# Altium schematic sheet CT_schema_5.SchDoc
size 430 x 414 mm
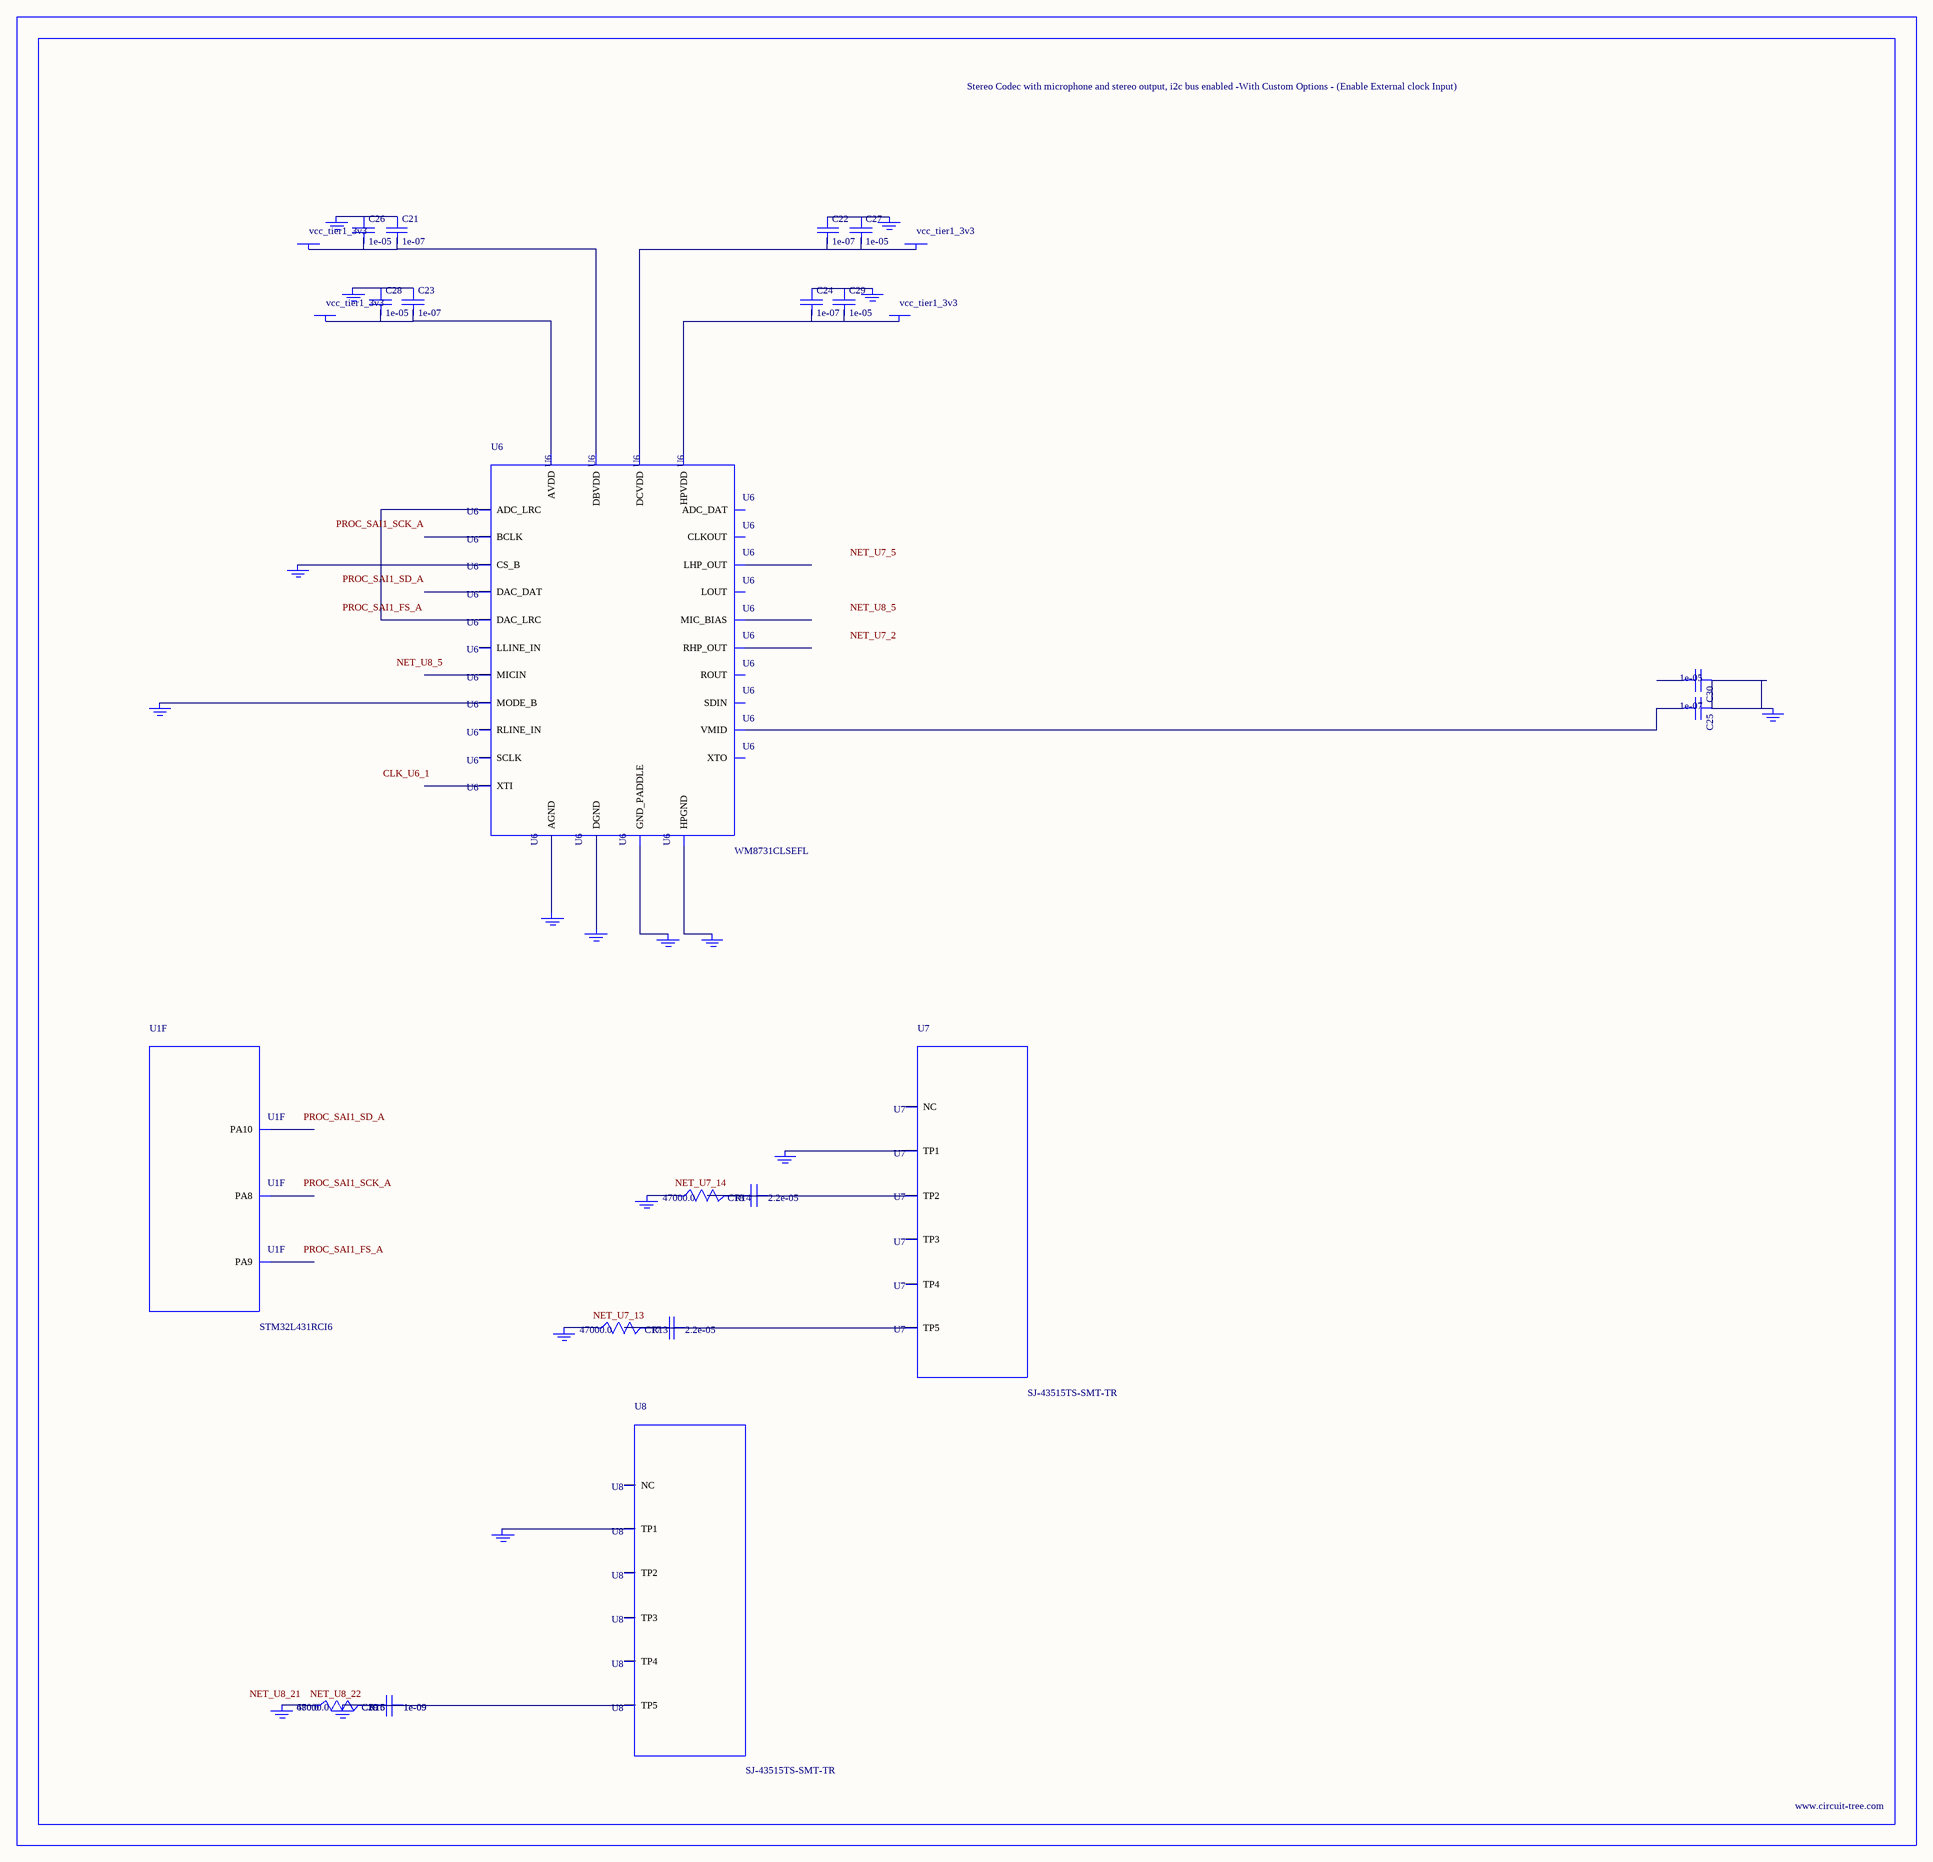
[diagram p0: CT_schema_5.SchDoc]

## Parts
BORDER4  (no value)
C17  2.2e-05  [C1210]
C18  2.2e-05  [C1210]
C19  1e-09  [C0402]
C20  1e-09  [C0402]
C21  1e-07  [C0402]
C22  1e-07  [C0402]
C23  1e-07  [C0402]
C24  1e-07  [C0402]
C25  1e-07  [C0402]
C26  1e-05  [C0805]
C27  1e-05  [C0805]
C28  1e-05  [C0805]
C29  1e-05  [C0805]
C30  1e-05  [C0805]
GND_INSTANCE_4_0  (no value)
GND_INSTANCE_4_1  (no value)
GND_INSTANCE_4_2  (no value)
GND_INSTANCE_4_3  (no value)
GND_INSTANCE_4_4  (no value)
GND_INSTANCE_4_5  (no value)
GND_INSTANCE_4_6  (no value)
GND_INSTANCE_4_7  (no value)
GND_INSTANCE_4_8  (no value)
GND_INSTANCE_4_9  (no value)
GND_INSTANCE_4_10  (no value)
GND_INSTANCE_4_11  (no value)
GND_INSTANCE_4_12  (no value)
GND_INSTANCE_4_13  (no value)
GND_INSTANCE_4_14  (no value)
GND_INSTANCE_4_15  (no value)
GND_INSTANCE_4_16  (no value)
POWER_INSTANCE_4_0  vcc_tier1_3v3
POWER_INSTANCE_4_1  vcc_tier1_3v3
POWER_INSTANCE_4_2  vcc_tier1_3v3
POWER_INSTANCE_4_3  vcc_tier1_3v3
R13  47000.0  [R0603]
R14  47000.0  [R0603]
R15  47000.0  [R0603]
R16  680.0  [R0603]
U1  STM32L431RCI6  [UFBGA64]  (part F of 6)
U6  WM8731CLSEFL  [QFN-28]
U7  SJ-43515TS-SMT-TR  [SJ-43515TS-SMT-TR]
U8  SJ-43515TS-SMT-TR  [SJ-43515TS-SMT-TR]

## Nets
NetC17_1: C17.1 C17.2 R13.2 U7.5(TP5)
NetC18_1: C18.1 C18.2 R14.2 U7.2(TP2)
NetC19_1: C19.1 C19.2 C20.1 C20.2 GND_INSTANCE_4_16.0(GND) R15.2 R16.2 U8.5(TP5)
NetC21_1: C21.1 C26.1 GND_INSTANCE_4_1.0(GND)
NetC21_2: C21.2 C26.2 POWER_INSTANCE_4_1.0(PWR) U6.5(DBVDD)
NetC22_1: C22.1 C27.1 GND_INSTANCE_4_0.0(GND)
NetC22_2: C22.2 C27.2 POWER_INSTANCE_4_0.0(PWR) U6.3(DCVDD)
NetC23_1: C23.1 C28.1 GND_INSTANCE_4_4.0(GND)
NetC23_2: C23.2 C28.2 POWER_INSTANCE_4_3.0(PWR) U6.18(AVDD)
NetC24_1: C24.1 C29.1 GND_INSTANCE_4_2.0(GND)
NetC24_2: C24.2 C29.2 POWER_INSTANCE_4_2.0(PWR) U6.12(HPVDD)
NetC25_1: C25.1 C30.1 GND_INSTANCE_4_5.0(GND)
NetC25_2: C25.2 U6.20(VMID)
NetGND_INSTANCE_4_3_0: GND_INSTANCE_4_3.0(GND) U6.15(HPGND)
NetGND_INSTANCE_4_6_0: GND_INSTANCE_4_6.0(GND) U6.25(MODE_B)
NetGND_INSTANCE_4_7_0: GND_INSTANCE_4_7.0(GND) U6.26(CS_B)
NetGND_INSTANCE_4_8_0: GND_INSTANCE_4_8.0(GND) U6.29(GND_PADDLE)
NetGND_INSTANCE_4_9_0: GND_INSTANCE_4_9.0(GND) U6.4(DGND)
NetGND_INSTANCE_4_10_0: GND_INSTANCE_4_10.0(GND) U6.19(AGND)
NetGND_INSTANCE_4_11_0: GND_INSTANCE_4_11.0(GND) U7.1(TP1)
NetGND_INSTANCE_4_12_0: GND_INSTANCE_4_12.0(GND) R14.1
NetGND_INSTANCE_4_13_0: GND_INSTANCE_4_13.0(GND) R13.1
NetGND_INSTANCE_4_14_0: GND_INSTANCE_4_14.0(GND) U8.1(TP1)
NetGND_INSTANCE_4_15_0: GND_INSTANCE_4_15.0(GND) R15.1 R16.1
NetU6_9: U6.9(DAC_LRC) U6.11(ADC_LRC)

Not connected (* = marked no-connect by the designer): C30 2; U1 C6(PA10) C7(PA9) D7(PA8); U6 1(XTI) 2(XTO) 6(CLKOUT) 7(BCLK) 8(DAC_DAT) 10(ADC_DAT) 13(LHP_OUT) 14(RHP_OUT) 16(LOUT) 17(ROUT) 21(MIC_BIAS) 22(MICIN) 23(RLINE_IN) 24(LLINE_IN) 27(SDIN) 28(SCLK); U7 3(TP3) 4(TP4) 6(NC); U8 2(TP2) 3(TP3) 4(TP4) 6(NC)

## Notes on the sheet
- Labels drawn without touching a wire or pin: CLK_U6_1, NET_U7_2, NET_U7_5, NET_U7_13, NET_U7_14, NET_U8_5, NET_U8_21, NET_U8_22, PROC_SAI1_FS_A, PROC_SAI1_SCK_A, PROC_SAI1_SD_A

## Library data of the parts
BORDER4 = BORDER_PAGE4
C17 C18 = C1210C224K5RACTU
C19 C20 = C0402C102K3RAC
C21-C25 = C0402C104K3RACTU
C26-C30 = C0805C106K8RACTU
GND_INSTANCE_4_0-GND_INSTANCE_4_16 = GND
POWER_INSTANCE_4_0-POWER_INSTANCE_4_3 = PWR
R13-R15 = RC0603JR-0747KL
R16 = RC0603JR-07680RL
